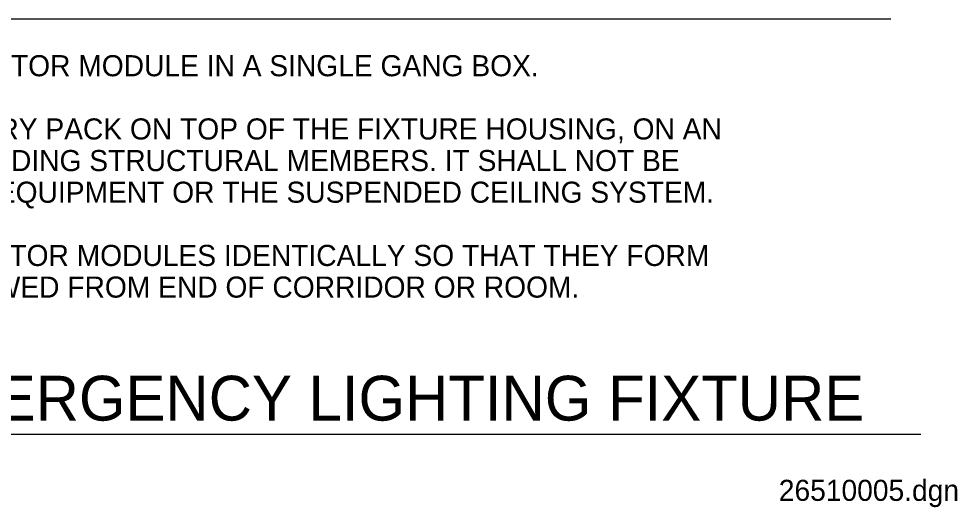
# Model space of a CAD drawing. Extents: x -12093.1 to -12048.3, y -12283.2 to -12238.8.
import ezdxf

# ---------------------------------------------------------------- set-up
doc = ezdxf.new("R2010")
doc.units = 0
doc.layers.add('G-ANNO-TEXT', color=7, linetype='Continuous')

msp = doc.modelspace()

# ---------------------------------------------------------------- linework, layer by layer
at = {"layer": 'G-ANNO-TEXT'}
for p, q in [((-12092.923, -12267.707), (-12050.359, -12267.707)), ((-12092.503, -12280.845), (-12049.41, -12280.845))]:
    msp.add_line(p, q, dxfattribs=at)

# ---------------------------------------------------------------- texts
for s, height, p in [('INSTALL REMOTE TEST/MONITOR MODULE IN A SINGLE GANG BOX.', 0.66667, (-12090.973, -12269.524)), ('MOUNT EMERGENCY BATTERY PACK ON TOP OF THE FIXTURE HOUSING, ON AN', 0.66667, (-12090.973, -12271.524)), ('ADJACENT WALL OR ON BUILDING STRUCTURAL MEMBERS. IT SHALL NOT BE', 0.66667, (-12090.973, -12272.524)), ('MOUNTED TO MECHANICAL EQUIPMENT OR THE SUSPENDED CEILING SYSTEM.', 0.66667, (-12090.973, -12273.524)), ('LOCATE REMOTE TEST/MONITOR MODULES IDENTICALLY SO THAT THEY FORM', 0.66667, (-12090.973, -12275.524)), ('A STRAIGHT LINE WHEN VIEWED FROM END OF CORRIDOR OR ROOM.', 0.66667, (-12090.973, -12276.524)), ('RECESSED EMERGENCY LIGHTING FIXTURE', 1.41667, (-12092.465, -12280.413)), ('26510005.dgn', 0.66667, (-12053.905, -12282.952))]:
    msp.add_text(s, height=height, dxfattribs=at).set_placement(p)

doc.saveas('drawing.dxf')
